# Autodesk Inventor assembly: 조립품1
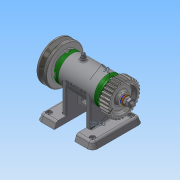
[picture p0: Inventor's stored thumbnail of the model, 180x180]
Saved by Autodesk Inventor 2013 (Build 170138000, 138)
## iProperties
Created: 2016-07
Part Number: 조립품1
Document SubType Name: Assembly
Designer: Administrator
Author: Administrator
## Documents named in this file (16)
- C:\Users\Administrator\Desktop\460707V1014\조립품1.iam
- C:\Users\Administrator\Desktop\460707V1014\V벨트풀리.ipt
- C:\Users\Administrator\Desktop\460707V1014\너트 M 8.ipt
- C:\Users\Administrator\Desktop\460707V1014\니플 M 6 x 0.75.ipt
- C:\Users\Administrator\Desktop\460707V1014\베어링 15 x 32 x 9.ipt
- C:\Users\Administrator\Desktop\460707V1014\볼트 M 6 x 8.ipt
- C:\Users\Administrator\Desktop\460707V1014\볼트 M4 x 12.ipt
- C:\Users\Administrator\Desktop\460707V1014\부품2.ipt
- C:\Users\Administrator\Desktop\460707V1014\스퍼기어.ipt
- C:\Users\Administrator\Desktop\460707V1014\스프링와셔 8.ipt
- C:\Users\Administrator\Desktop\460707V1014\오일 실 15 25 7.ipt
- C:\Users\Administrator\Desktop\460707V1014\와셔 6x11.5.ipt
- C:\Users\Administrator\Desktop\460707V1014\와셔 8x17.ipt
- C:\Users\Administrator\Desktop\460707V1014\축.ipt
- C:\Users\Administrator\Desktop\460707V1014\커버.ipt
- C:\Users\Administrator\Desktop\460707V1014\키 3 x 3 x 12.ipt
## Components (11 placed, 3 different names)
1. V벨트풀리:1
2. KS B 2023 6002 - 15 x 32 x 9:1
3. KS B 2023 6002 - 15 x 32 x 9:2
4. ISO 4762 M4 x 12:2
5. ISO 4762 M4 x 12:3
6. ISO 4762 M4 x 12:4
7. ISO 4762 M4 x 12:5
8. ISO 4762 M4 x 12:1
9. ISO 4762 M4 x 12:6
10. ISO 4762 M4 x 12:7
11. ISO 4762 M4 x 12:8
